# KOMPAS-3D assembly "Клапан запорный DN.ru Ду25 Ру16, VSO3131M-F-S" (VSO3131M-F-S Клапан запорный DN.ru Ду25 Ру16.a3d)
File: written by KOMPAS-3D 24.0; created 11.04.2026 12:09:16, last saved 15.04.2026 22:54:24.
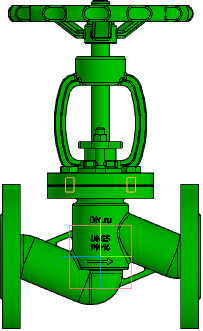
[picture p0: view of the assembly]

Document properties: Автор: R2D2; Полное имя файла: E:\Работа\Зайцев\VSO3131M-F-S Клапан запорный DN.ru Ду15-100 Ру16\DN25\исходные материалы\VSO3131M-F-S Клапан запорный DN.ru Ду25 Ру16.a3d

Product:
- Component [detail]: Корпус  | qty 1  | pos. 1  | Масса: 6.9; Автор: R2D2; source file: Корпус.m3d
- Component [detail]: Сборка  | qty 1  | pos. 2  | Масса: 1.450691; Автор: R2D2; source file: 2.m3d
- Component [standard]: Hexagon head screw ISO 4017 - М8 x 16  | qty 4  | Масса: 0.012085; Раздел спецификации: Стандартные изделия; Рассекать на разрезах: no
- Part/product: Клапан запорный DN.ru Ду25 Ру16  | designation VSO3131M-F-S
    Масса: 5.1
    Раздел спецификации: Прочие изделия
    Примечание: D090-02948

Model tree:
1. Массив по концентрической сетке:1  (with: Грань.Элемент вращения:2, Грань.Операция без истории:1)  (labels: Грань.Элемент выдавливания:9.Экземпляр ( 1, 3 ))  (4 pattern instances)
     Шаг 2 = 360; Расстояние = -200

Referenced files in E:\Работа\Зайцев\VSO3131M-F-S Клапан запорный DN.ru Ду15-100 Ру40\DN25\исходные материалы\: Корпус.m3d, 2.m3d
Referenced files in E:\Работа\Зайцев\VSO3131M-F-S Клапан запорный DN.ru Ду15-100 Ру16\DN25\исходные материалы\: Корпус.m3d, 2.m3d
Referenced files in C:\Program Files\ASCON\KOMPAS-3D v24\Libs\PolynomLib\DATA\vault\Methods\Kompas\3D\: PLib_Bolt_1_ISO_1100.m3d
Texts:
  Hexagon head screw
  BOSimple***PART:17775d1c-e7de-f283-40f0-d40789f7f59e***SHORTLOC:A259_7B16EF33AB1642D2[13;1,25;16;8;-;Undefined]
  Программные изделия  и базы данных
  VSO3131M-F-S
  Точка начала. Х
  Точка начала. Y
  Точка начала. Z
  Hexagon head screw ISO 4017 - М8 x 16 (1)
  hole1
  hole2
  Hexagon head screw ISO 4017 - М8 x 16 (2)
  Hexagon head screw ISO 4017 - М8 x 16 (3)
  Hexagon head screw ISO 4017 - М8 x 16 (4)
  Ось Z.Начало координат
  Ось Y.Начало координат
  Плоскость XY.Начало координат
  Плоскость ZY.Начало координат
  Плоскость ZX.Начало координат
